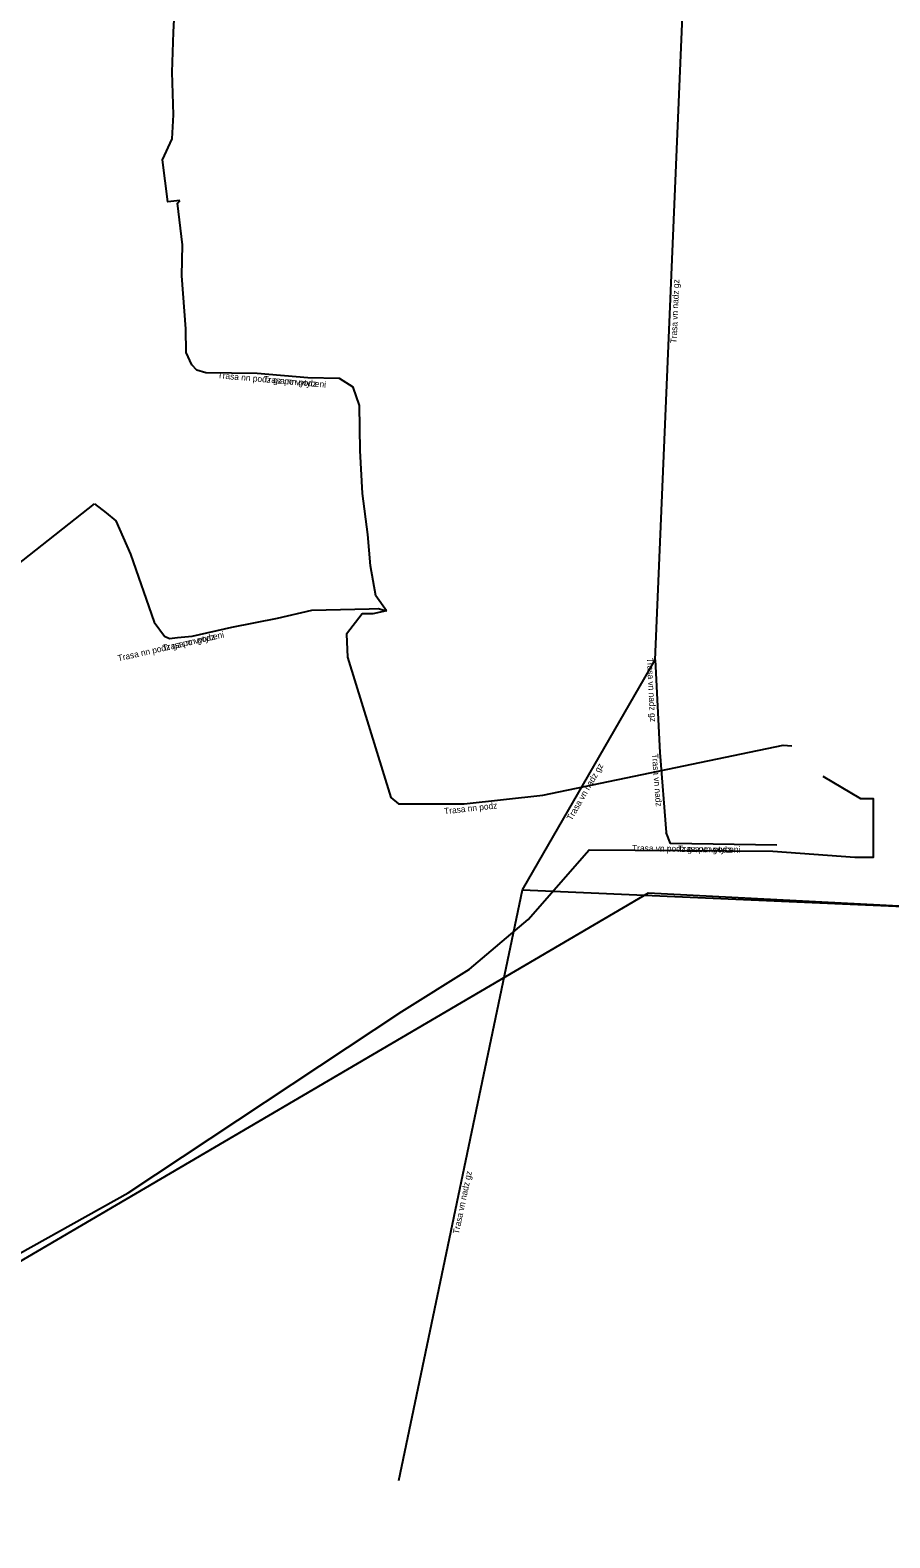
# Model space of a CAD drawing. Extents: x -470004 to -469564, y -1099117 to -1098659.
# Drawn here: x -469695.6 to -469626.9, y -1098937.9 to -1098817.3 of the extents above; entities that cross this region are included whole.
import ezdxf

# ---------------------------------------------------------------- set-up
doc = ezdxf.new("R2010")
doc.units = 0
for name, color, linetype in [('Popiskový text - Ostatní atributy Trasy', 7, 'Continuous'), ('Spojnice NN', 7, 'Continuous'), ('Spojnice VN', 7, 'Continuous')]:
    doc.layers.add(name, color=color, linetype=linetype)

msp = doc.modelspace()

# ---------------------------------------------------------------- linework, layer by layer
at = {"layer": 'Spojnice NN'}
for points in [[(-469683.63, -1098830.93), (-469684.58, -1098831.05), (-469685.01, -1098827.69), (-469684.25, -1098826.02), (-469684.14, -1098824.09), (-469684.24, -1098820.68), (-469684.14, -1098817.47), (-469684.01, -1098814.94)], [(-469683.63, -1098830.93), (-469684.58, -1098831.05), (-469685.01, -1098827.69), (-469684.25, -1098826.02), (-469684.14, -1098824.09), (-469684.24, -1098820.68), (-469684.14, -1098817.47), (-469684.01, -1098814.94)], [(-469603.33, -1098889.47), (-469604.54, -1098889.41), (-469608.66, -1098888.27), (-469646.19, -1098886.31), (-469704.92, -1098920.74), (-469761.36, -1098820.29), (-469764.71, -1098821.99), (-469767.9, -1098819.17)], [(-469667.12, -1098863.73), (-469667.96, -1098862.55), (-469668.38, -1098860.14), (-469668.61, -1098857.63), (-469669.04, -1098854.35), (-469669.23, -1098850.93), (-469669.28, -1098847.32), (-469669.78, -1098845.86), (-469670.88, -1098845.18), (-469673.4, -1098845.12), (-469677.44, -1098844.77), (-469681.54, -1098844.73), (-469682.26, -1098844.51), (-469682.68, -1098844.07), (-469683.13, -1098843.09), (-469683.16, -1098841.19), (-469683.47, -1098836.95), (-469683.42, -1098834.48), (-469683.82, -1098831.16), (-469683.63, -1098830.93)], [(-469667.12, -1098863.73), (-469667.96, -1098862.55), (-469668.38, -1098860.14), (-469668.61, -1098857.63), (-469669.04, -1098854.35), (-469669.23, -1098850.93), (-469669.28, -1098847.32), (-469669.78, -1098845.86), (-469670.88, -1098845.18), (-469673.4, -1098845.12), (-469677.44, -1098844.77), (-469681.54, -1098844.73), (-469682.26, -1098844.51), (-469682.68, -1098844.07), (-469683.13, -1098843.09), (-469683.16, -1098841.19), (-469683.47, -1098836.95), (-469683.42, -1098834.48), (-469683.82, -1098831.16), (-469683.63, -1098830.93)], [(-469708.6, -1098869.5), (-469690.44, -1098855.19)], [(-469690.44, -1098855.19), (-469689.53, -1098855.92), (-469688.74, -1098856.55), (-469687.58, -1098859.21), (-469685.69, -1098864.64), (-469684.86, -1098865.77), (-469684.46, -1098865.95), (-469683.83, -1098865.88), (-469682.64, -1098865.78), (-469679.47, -1098865.06), (-469675.83, -1098864.34), (-469673.09, -1098863.68), (-469668.49, -1098863.57), (-469667.77, -1098863.56), (-469667.12, -1098863.73)], [(-469690.44, -1098855.19), (-469689.53, -1098855.92), (-469688.74, -1098856.55), (-469687.58, -1098859.21), (-469685.69, -1098864.64), (-469684.86, -1098865.77), (-469684.46, -1098865.95), (-469683.83, -1098865.88), (-469682.64, -1098865.78), (-469679.47, -1098865.06), (-469675.83, -1098864.34), (-469673.09, -1098863.68), (-469668.49, -1098863.57), (-469667.77, -1098863.56), (-469667.12, -1098863.73)], [(-469667.12, -1098863.73), (-469668.21, -1098863.98), (-469669.06, -1098863.98), (-469670.32, -1098865.62), (-469670.23, -1098867.45), (-469666.76, -1098878.66), (-469666.15, -1098879.18), (-469660.9, -1098879.18), (-469654.62, -1098878.47), (-469635.4, -1098874.49), (-469634.72, -1098874.53)]]:
    msp.add_lwpolyline(points, dxfattribs=at)
at = {"layer": 'Spojnice VN'}
for points in [[(-469645.64, -1098867.66), (-469643.17, -1098809.25)], [(-469656.23, -1098886.04), (-469645.64, -1098867.66)], [(-469645.64, -1098867.66), (-469645.26, -1098875.08)], [(-469645.26, -1098875.08), (-469644.77, -1098881.47)], [(-469749.37, -1098945.26), (-469705.52, -1098918.67), (-469699.92, -1098917.03), (-469687.75, -1098910.28), (-469665.89, -1098895.77), (-469660.49, -1098892.4), (-469655.78, -1098888.43), (-469650.9, -1098882.85), (-469636.22, -1098882.96), (-469629.68, -1098883.44), (-469628.18, -1098883.44), (-469628.18, -1098878.78), (-469629.2, -1098878.78), (-469632.2, -1098876.98)], [(-469749.37, -1098945.26), (-469705.52, -1098918.67), (-469699.92, -1098917.03), (-469687.75, -1098910.28), (-469665.89, -1098895.77), (-469660.49, -1098892.4), (-469655.78, -1098888.43), (-469650.9, -1098882.85), (-469636.22, -1098882.96), (-469629.68, -1098883.44), (-469628.18, -1098883.44), (-469628.18, -1098878.78), (-469629.2, -1098878.78), (-469632.2, -1098876.98)], [(-469635.92, -1098882.47), (-469644.41, -1098882.35), (-469644.77, -1098881.47)], [(-469635.92, -1098882.47), (-469644.41, -1098882.35), (-469644.77, -1098881.47)], [(-469666.12, -1098933.27), (-469656.23, -1098886.04)], [(-469656.23, -1098886.04), (-469565.46, -1098890.03)]]:
    msp.add_lwpolyline(points, dxfattribs=at)

# ---------------------------------------------------------------- texts
at = {"layer": 'Popiskový text - Ostatní atributy Trasy'}
for s, rotation, p in [('Trasa vn nadz gz', 87.5786, (-469643.92, -1098842.37)), ('Trasa nn podz gz po vytyceni', 355.0486, (-469680.63, -1098845.15)), ('Trasa nn podz', 355.0486, (-469676.96, -1098845.46)), ('Trasa nn podz gz po vytyceni', 12.7965, (-469688.54, -1098867.79)), ('Trasa nn podz', 12.7965, (-469684.94, -1098866.97)), ('Trasa vn nadz gz', 272.9317, (-469646.3, -1098867.51)), ('Trasa vn nadz gz', 60.0588, (-469652.31, -1098880.55)), ('Trasa vn nadz', 274.3966, (-469645.9, -1098875.18)), ('Trasa nn podz', 6.3852, (-469662.48, -1098880.01)), ('Trasa vn podz gz po vytyceni', 359.1496, (-469647.49, -1098882.95)), ('Trasa vn podz', 359.1496, (-469643.8, -1098883.01)), ('Trasa vn nadz gz', 78.1687, (-469661.33, -1098913.6))]:
    msp.add_text(s, height=0.5, rotation=rotation, dxfattribs=at).set_placement(p)

doc.saveas('drawing.dxf')
